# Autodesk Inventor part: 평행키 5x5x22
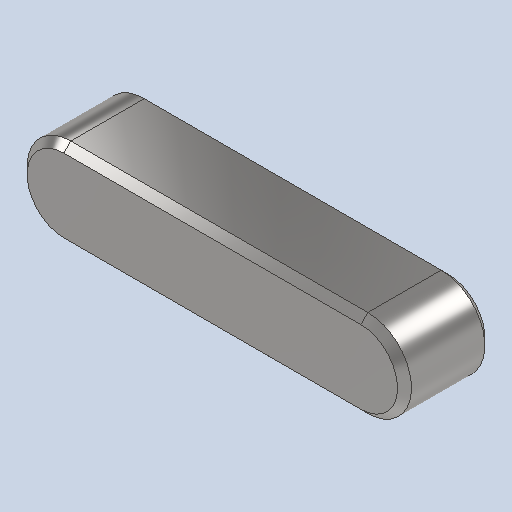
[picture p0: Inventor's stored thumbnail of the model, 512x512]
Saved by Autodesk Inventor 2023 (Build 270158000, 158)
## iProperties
Created: 2024-09
Part Number: 평행키 5x5x22
Material: 강철, 연강
Description: 키 및 해당 키홈
Document SubType Name: Modeling
Designer: home
Density: 7.85 g/cm^3
Appearance: 기본값
Author: jhkim
Sending System: Autodesk Inventor 2025
Preprocessor: ST-DEVELOPER v20
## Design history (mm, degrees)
feature "Solid1"
node "솔리드1"
